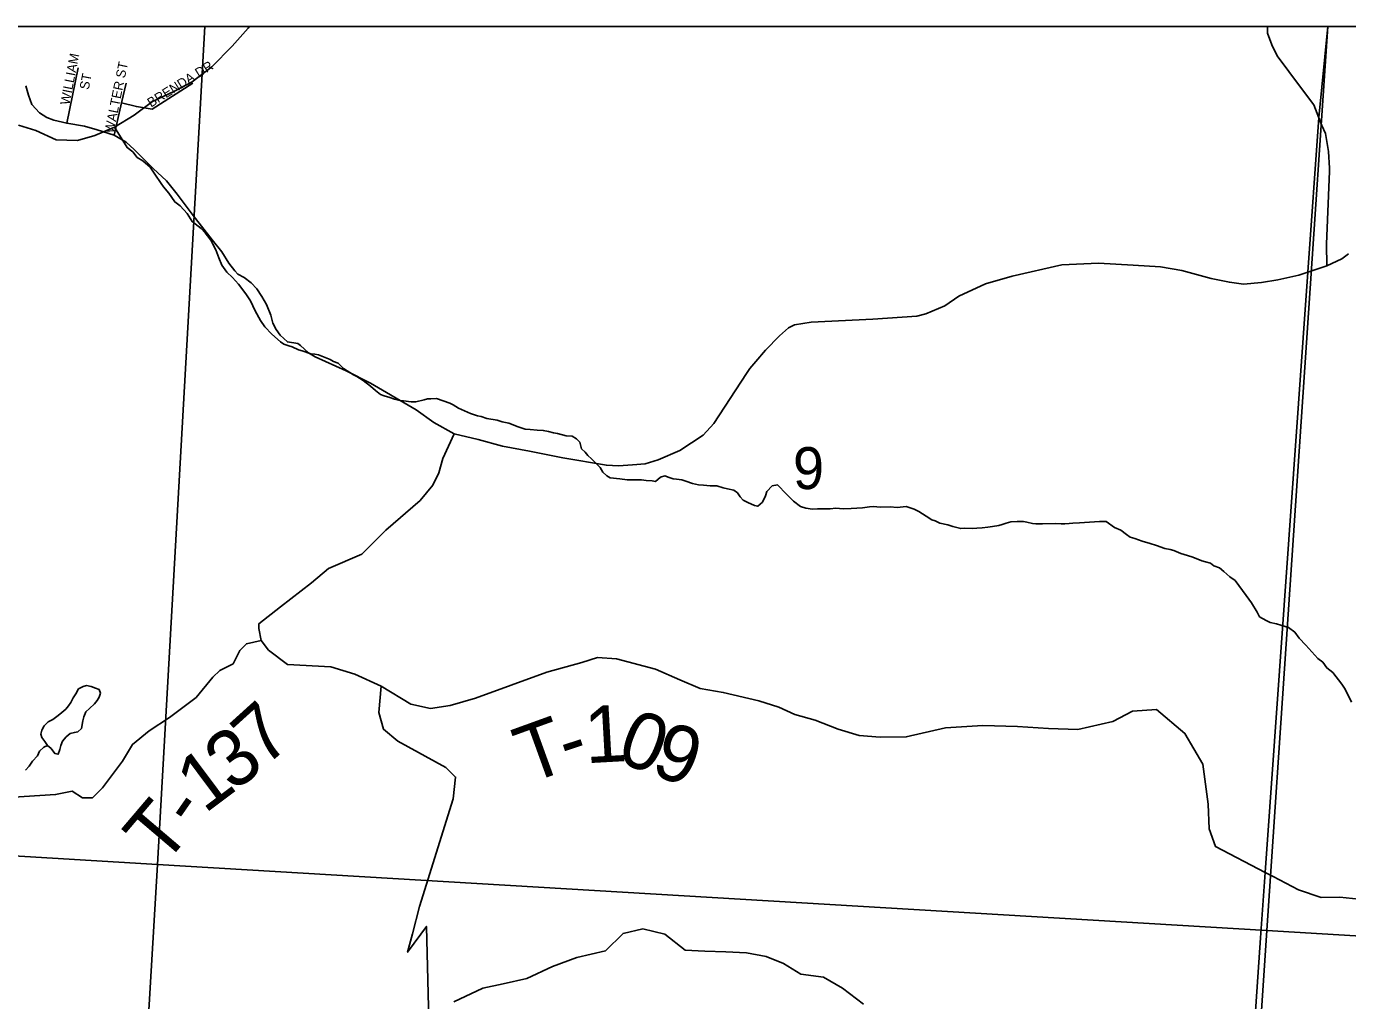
# Model space of a CAD drawing. Extents: x 1949938.81 to 1949945.61, y 152207.65 to 152214.09.
# Drawn here: x 1949941.382 to 1949942.704, y 152213.113 to 152214.087 of the extents above; entities that cross this region are included whole.
import ezdxf

# ---------------------------------------------------------------- set-up
doc = ezdxf.new("R2010")
doc.units = 0
for name, color, linetype in [('GM_X_County', 7, 'Continuous'), ('GM_X_County_Road', 7, 'Continuous'), ('GM_X_Minor_River', 7, 'Continuous'), ('GM_X_Section', 7, 'Continuous'), ('GM_X_Section_Text', 7, 'Continuous'), ('GM_X_State_Route', 7, 'Continuous'), ('GM_X_Township', 7, 'Continuous'), ('GM_X_Township_Road', 7, 'Continuous'), ('GM_X_Township_Road_Text', 7, 'Continuous'), ('GM_X_Township_ROW', 7, 'Continuous'), ('GM_X_Township_Subdivision', 7, 'Continuous'), ('GM_X_Township_Subdivision_Text', 7, 'Continuous')]:
    doc.layers.add(name, color=color, linetype=linetype)

msp = doc.modelspace()

# ---------------------------------------------------------------- linework, layer by layer
at = {"layer": 'GM_X_County'}
msp.add_lwpolyline([(1949945.6069, 152208.8266), (1949945.6069, 152214.0874), (1949938.8069, 152214.0874), (1949938.8069, 152213.1813)], dxfattribs=at)
at = {"layer": 'GM_X_County_Road'}
for points in [[(1949941.7645, 152213.1629), (1949941.7635, 152213.1615), (1949941.7683, 152213.1799), (1949941.7755, 152213.2071), (1949941.8091, 152213.315), (1949941.8115, 152213.3366), (1949941.8019, 152213.3462), (1949941.7539, 152213.3726), (1949941.7395, 152213.3845), (1949941.7347, 152213.4013), (1949941.7371, 152213.4277), (1949941.7107, 152213.4397), (1949941.6867, 152213.4469), (1949941.6435, 152213.4493), (1949941.6244, 152213.4637), (1949941.6172, 152213.4732), (1949941.6148, 152213.4852), (1949941.6148, 152213.49), (1949941.6363, 152213.5068), (1949941.6675, 152213.5308), (1949941.6843, 152213.5452), (1949941.7179, 152213.5596), (1949941.7419, 152213.5836), (1949941.7762, 152213.6134), (1949941.7888, 152213.6286), (1949941.7949, 152213.6409), (1949941.7989, 152213.6553), (1949941.8103, 152213.6801)], [(1949941.7851, 152213.08), (1949941.7823, 152213.1873), (1949941.7645, 152213.1629)]]:
    msp.add_lwpolyline(points, dxfattribs=at)
at = {"layer": 'GM_X_Minor_River'}
for points in [[(1949941.3743, 152213.9886), (1949941.3917, 152213.9832), (1949941.4121, 152213.974), (1949941.4333, 152213.9732), (1949941.4508, 152213.9784), (1949941.4705, 152213.9867), (1949941.4902, 152213.9988), (1949941.5085, 152214.0124), (1949941.5297, 152214.0222), (1949941.5479, 152214.032), (1949941.5677, 152214.0471), (1949941.5882, 152214.0675), (1949941.6042, 152214.0857), (1949941.6053, 152214.0874)], [(1949941.4705, 152213.9867), (1949941.483, 152213.9663), (1949941.4886, 152213.962), (1949941.4931, 152213.9562), (1949941.4987, 152213.9531), (1949941.5062, 152213.9465), (1949941.5106, 152213.9396), (1949941.5169, 152213.9304), (1949941.5195, 152213.9269), (1949941.5247, 152213.9208), (1949941.5306, 152213.9119), (1949941.5362, 152213.908), (1949941.5429, 152213.9003), (1949941.548, 152213.8923), (1949941.557, 152213.8853), (1949941.5611, 152213.881), (1949941.5666, 152213.8737), (1949941.5688, 152213.8695), (1949941.5718, 152213.8638), (1949941.5747, 152213.8561), (1949941.5779, 152213.8485), (1949941.5827, 152213.8416), (1949941.5883, 152213.8362), (1949941.5943, 152213.8296), (1949941.6017, 152213.82), (1949941.6065, 152213.8131), (1949941.6112, 152213.8031), (1949941.6164, 152213.7932), (1949941.6208, 152213.787), (1949941.6279, 152213.7797), (1949941.6364, 152213.7719), (1949941.6398, 152213.7696), (1949941.6447, 152213.768), (1949941.6481, 152213.7668), (1949941.6545, 152213.764), (1949941.6582, 152213.7628), (1949941.6669, 152213.76), (1949941.6707, 152213.7596), (1949941.6745, 152213.7588), (1949941.6793, 152213.7568), (1949941.6861, 152213.7544), (1949941.6895, 152213.7524), (1949941.694, 152213.7505), (1949941.6996, 152213.7454), (1949941.7093, 152213.7388), (1949941.7127, 152213.7372), (1949941.7191, 152213.7333), (1949941.7266, 152213.7275), (1949941.7314, 152213.7233), (1949941.7363, 152213.7194), (1949941.74, 152213.7178), (1949941.7457, 152213.7162), (1949941.7506, 152213.7146), (1949941.7559, 152213.7134), (1949941.7593, 152213.7129), (1949941.7672, 152213.712), (1949941.7717, 152213.712), (1949941.7801, 152213.7141), (1949941.7835, 152213.7148), (1949941.7869, 152213.7151), (1949941.7923, 152213.7154), (1949941.8058, 152213.7106), (1949941.8092, 152213.7091), (1949941.8144, 152213.7056), (1949941.8204, 152213.7028), (1949941.8265, 152213.7004), (1949941.8336, 152213.698), (1949941.837, 152213.6972), (1949941.8427, 152213.6952), (1949941.8532, 152213.6935), (1949941.8581, 152213.6919), (1949941.8649, 152213.6907), (1949941.8743, 152213.6871), (1949941.8811, 152213.6847), (1949941.886, 152213.6842), (1949941.8932, 152213.6837), (1949941.8993, 152213.6833), (1949941.9045, 152213.6824), (1949941.9094, 152213.6808), (1949941.9136, 152213.6804), (1949941.9223, 152213.6779), (1949941.9283, 152213.6775), (1949941.9324, 152213.6751), (1949941.9358, 152213.6716), (1949941.9376, 152213.6651), (1949941.9413, 152213.6617), (1949941.9439, 152213.6582), (1949941.9476, 152213.6551), (1949941.9562, 152213.6462), (1949941.9588, 152213.6416), (1949941.9629, 152213.6378), (1949941.9662, 152213.6358), (1949941.9757, 152213.6349), (1949941.9832, 152213.634), (1949941.9976, 152213.6338), (1949942.0022, 152213.6333), (1949942.0082, 152213.6328), (1949942.0116, 152213.6324), (1949942.0166, 152213.6365)], [(1949942.0166, 152213.6365), (1949942.0208, 152213.6379), (1949942.0253, 152213.6363), (1949942.0291, 152213.6351), (1949942.0325, 152213.6347), (1949942.0378, 152213.6339), (1949942.0419, 152213.6327), (1949942.0487, 152213.6303), (1949942.0544, 152213.629), (1949942.0597, 152213.6286), (1949942.0661, 152213.6281), (1949942.0729, 152213.628), (1949942.0793, 152213.626), (1949942.0835, 152213.6251), (1949942.0899, 152213.6235), (1949942.0936, 152213.6208), (1949942.0962, 152213.6169), (1949942.0992, 152213.6135), (1949942.104, 152213.6111), (1949942.1104, 152213.6084), (1949942.1138, 152213.6075), (1949942.1184, 152213.6116), (1949942.1216, 152213.618), (1949942.1228, 152213.6222), (1949942.1282, 152213.6278), (1949942.1335, 152213.6289), (1949942.1425, 152213.6196), (1949942.1495, 152213.6126), (1949942.1566, 152213.6072), (1949942.1619, 152213.6056), (1949942.1687, 152213.6047), (1949942.1736, 152213.605), (1949942.1861, 152213.6048), (1949942.1918, 152213.6055), (1949942.1994, 152213.605), (1949942.2073, 152213.6052), (1949942.2187, 152213.6058), (1949942.2256, 152213.6068), (1949942.2294, 152213.6071), (1949942.2365, 152213.6066), (1949942.2464, 152213.6068), (1949942.2532, 152213.6064), (1949942.2623, 152213.6073), (1949942.2702, 152213.6046), (1949942.2751, 152213.6022), (1949942.2822, 152213.5975), (1949942.2878, 152213.594), (1949942.2912, 152213.5928), (1949942.2961, 152213.5905), (1949942.304, 152213.5888), (1949942.3089, 152213.5872), (1949942.3168, 152213.5852), (1949942.3203, 152213.5855), (1949942.3286, 152213.5854), (1949942.3328, 152213.5857), (1949942.3384, 152213.5859), (1949942.3438, 152213.5866), (1949942.3487, 152213.5873), (1949942.3548, 152213.5883), (1949942.3582, 152213.5894), (1949942.3624, 152213.5905), (1949942.367, 152213.5919), (1949942.3734, 152213.5922), (1949942.3795, 152213.5921), (1949942.3829, 152213.5917), (1949942.3885, 152213.5904), (1949942.3919, 152213.59), (1949942.3987, 152213.5899), (1949942.4116, 152213.5904), (1949942.4173, 152213.5899), (1949942.4211, 152213.5899), (1949942.4253, 152213.5902), (1949942.4291, 152213.5905), (1949942.4355, 152213.5908), (1949942.4457, 152213.5917), (1949942.4556, 152213.5923), (1949942.4624, 152213.5922), (1949942.4706, 152213.5864), (1949942.477, 152213.5836), (1949942.4826, 152213.5794), (1949942.4864, 152213.5766), (1949942.4909, 152213.5754), (1949942.4984, 152213.5726), (1949942.5063, 152213.5702), (1949942.5127, 152213.5682), (1949942.521, 152213.5654), (1949942.5263, 152213.5642), (1949942.5301, 152213.5634), (1949942.5369, 152213.5602), (1949942.5436, 152213.5582), (1949942.5489, 152213.5566), (1949942.5579, 152213.553), (1949942.5617, 152213.5518), (1949942.5666, 152213.5506), (1949942.57, 152213.5479), (1949942.5756, 152213.5459), (1949942.5801, 152213.5424), (1949942.5861, 152213.537), (1949942.5913, 152213.5331), (1949942.5987, 152213.5231), (1949942.6024, 152213.5181)], [(1949942.6024, 152213.5181), (1949942.6076, 152213.5108), (1949942.6135, 152213.5016), (1949942.6157, 152213.497), (1949942.6224, 152213.4931), (1949942.6265, 152213.4911), (1949942.6326, 152213.4899), (1949942.6371, 152213.4887), (1949942.6446, 152213.4863), (1949942.651, 152213.4816), (1949942.6554, 152213.4755), (1949942.6621, 152213.4685), (1949942.674, 152213.4554), (1949942.6792, 152213.4515), (1949942.6829, 152213.4458), (1949942.6889, 152213.4411), (1949942.6982, 152213.4296), (1949942.7015, 152213.4246), (1949942.7077, 152213.4115)], [(1949941.3812, 152213.3437), (1949941.385, 152213.3475), (1949941.3885, 152213.3527), (1949941.3935, 152213.358), (1949941.3955, 152213.3625), (1949941.3997, 152213.3666), (1949941.4032, 152213.3684), (1949941.4006, 152213.3723), (1949941.3976, 152213.3761), (1949941.3966, 152213.3795), (1949941.3978, 152213.3837), (1949941.4001, 152213.3878), (1949941.404, 152213.392), (1949941.4086, 152213.3941), (1949941.4139, 152213.3982), (1949941.4178, 152213.4012), (1949941.4216, 152213.4046), (1949941.4243, 152213.4079), (1949941.4267, 152213.4113), (1949941.429, 152213.4158), (1949941.4317, 152213.42), (1949941.4345, 152213.4249), (1949941.4391, 152213.4274)], [(1949941.4391, 152213.4274), (1949941.4425, 152213.4281), (1949941.447, 152213.4273), (1949941.4515, 152213.4257), (1949941.4549, 152213.4241), (1949941.4564, 152213.4207), (1949941.4552, 152213.4165), (1949941.4532, 152213.4131), (1949941.4505, 152213.4098), (1949941.4455, 152213.4053), (1949941.4417, 152213.4019), (1949941.4397, 152213.397), (1949941.4388, 152213.3929), (1949941.4372, 152213.3853), (1949941.4337, 152213.382), (1949941.4303, 152213.3813), (1949941.4261, 152213.3802), (1949941.4219, 152213.3768), (1949941.4184, 152213.3727), (1949941.4168, 152213.3682), (1949941.4156, 152213.3644), (1949941.414, 152213.3595), (1949941.4106, 152213.3603), (1949941.4069, 152213.3653), (1949941.4032, 152213.3684)], [(1949941.8099, 152213.1118), (1949941.8388, 152213.1254), (1949941.8592, 152213.1299), (1949941.8827, 152213.1351), (1949941.9085, 152213.1472), (1949941.9328, 152213.1562), (1949941.9616, 152213.1629), (1949941.9791, 152213.1803), (1949941.9988, 152213.1848), (1949942.0208, 152213.1794), (1949942.0411, 152213.1634), (1949942.0608, 152213.1626), (1949942.082, 152213.1618), (1949942.1025, 152213.1609), (1949942.1222, 152213.1571), (1949942.1395, 152213.1502), (1949942.1569, 152213.1395), (1949942.1796, 152213.1364), (1949942.1985, 152213.1257), (1949942.2197, 152213.1097)]]:
    msp.add_lwpolyline(points, dxfattribs=at)
at = {"layer": 'GM_X_Section'}
for p, q in [((1949941.5608, 152214.0874), (1949940.4809, 152214.0874)), ((1949942.6841, 152214.0874), (1949941.5608, 152214.0874)), ((1949943.7893, 152214.0874), (1949942.6841, 152214.0874))]:
    msp.add_line(p, q, dxfattribs=at)
for points in [[(1949940.4809, 152214.0874), (1949940.4294, 152213.3146), (1949941.5133, 152213.2491), (1949941.5608, 152214.0874)], [(1949941.5608, 152214.0874), (1949941.5133, 152213.2491), (1949942.623, 152213.1832), (1949942.6841, 152214.0874)], [(1949942.6841, 152214.0874), (1949942.623, 152213.1832), (1949943.7308, 152213.1166), (1949943.7893, 152214.0874)]]:
    msp.add_lwpolyline(points, dxfattribs=at)
for points in [[(1949941.5133, 152213.2491), (1949941.4524, 152212.2232), (1949940.3609, 152212.2864), (1949940.4294, 152213.3146)], [(1949942.623, 152213.1832), (1949942.5545, 152212.1539), (1949941.4524, 152212.2232), (1949941.5133, 152213.2491)], [(1949943.7308, 152213.1166), (1949943.6665, 152212.0918), (1949942.5545, 152212.1539), (1949942.623, 152213.1832)]]:
    msp.add_lwpolyline(points, close=True, dxfattribs=at)
at = {"layer": 'GM_X_State_Route'}
for points in [[(1949941.3818, 152214.028), (1949941.3843, 152214.0185), (1949941.3878, 152214.0094), (1949941.3953, 152214.0009), (1949941.4026, 152213.9963), (1949941.4097, 152213.9938), (1949941.4226, 152213.9905), (1949941.4402, 152213.9876), (1949941.4531, 152213.984), (1949941.4699, 152213.9788), (1949941.4819, 152213.9715), (1949941.49, 152213.9644), (1949941.509, 152213.9454), (1949941.5224, 152213.933), (1949941.5332, 152213.9195), (1949941.549, 152213.8983), (1949941.5682, 152213.874), (1949941.5776, 152213.862), (1949941.5846, 152213.8505), (1949941.5906, 152213.8429), (1949941.5939, 152213.8395), (1949941.6002, 152213.8364), (1949941.607, 152213.8311), (1949941.6129, 152213.8251), (1949941.6179, 152213.8174), (1949941.6225, 152213.8093), (1949941.6269, 152213.7986), (1949941.6286, 152213.7906), (1949941.632, 152213.7844), (1949941.6362, 152213.7786), (1949941.6434, 152213.7719), (1949941.6536, 152213.7702), (1949941.6565, 152213.7683), (1949941.6644, 152213.7608), (1949941.671, 152213.7571), (1949941.7021, 152213.7429), (1949941.7266, 152213.7305), (1949941.7722, 152213.7041), (1949941.7899, 152213.6913), (1949941.8103, 152213.6801), (1949941.834, 152213.6743), (1949941.8585, 152213.6675), (1949941.8854, 152213.6625), (1949941.9188, 152213.6561), (1949941.9625, 152213.6486), (1949941.9746, 152213.6481), (1949941.9885, 152213.6488), (1949942.0012, 152213.6501), (1949942.0143, 152213.6539), (1949942.0358, 152213.6633), (1949942.0592, 152213.6787), (1949942.0698, 152213.6904), (1949942.1026, 152213.7402), (1949942.1059, 152213.7453), (1949942.112, 152213.7524)], [(1949942.112, 152213.7524), (1949942.1215, 152213.7635), (1949942.1356, 152213.7779), (1949942.1447, 152213.7858), (1949942.1507, 152213.7889), (1949942.1674, 152213.7915), (1949942.2288, 152213.7947), (1949942.2731, 152213.7977), (1949942.2818, 152213.7999), (1949942.3011, 152213.8079), (1949942.3151, 152213.8177), (1949942.3417, 152213.8298), (1949942.3682, 152213.8377), (1949942.4181, 152213.8491), (1949942.4546, 152213.8507), (1949942.4892, 152213.8487), (1949942.5166, 152213.8471), (1949942.5381, 152213.8434), (1949942.5674, 152213.8353), (1949942.5856, 152213.8315), (1949942.5998, 152213.8297), (1949942.6176, 152213.8313), (1949942.6339, 152213.834), (1949942.6552, 152213.8385), (1949942.6641, 152213.8415), (1949942.683, 152213.8479), (1949942.6982, 152213.855), (1949942.7048, 152213.8599)]]:
    msp.add_lwpolyline(points, dxfattribs=at)
at = {"layer": 'GM_X_Township'}
for points in [[(1949942.6839, 152214.0874), (1949938.8069, 152214.0874), (1949938.8069, 152213.1813)], [(1949942.6839, 152214.0874), (1949942.6751, 152213.9962), (1949942.6641, 152213.8415), (1949942.6215, 152213.2412), (1949942.6168, 152213.1758), (1949942.5466, 152212.148), (1949942.0825, 152212.1782), (1949941.5893, 152212.2102), (1949941.4472, 152212.2194), (1949941.3847, 152211.2124)], [(1949941.3847, 152211.2124), (1949941.4472, 152212.2194), (1949941.5893, 152212.2102), (1949942.0825, 152212.1782), (1949942.5466, 152212.148), (1949942.6168, 152213.1758), (1949942.6215, 152213.2412), (1949942.6641, 152213.8415), (1949942.6751, 152213.9962), (1949942.6839, 152214.0874)], [(1949945.6069, 152208.8266), (1949945.6069, 152214.0874), (1949942.6839, 152214.0874)]]:
    msp.add_lwpolyline(points, dxfattribs=at)
at = {"layer": 'GM_X_Township_Road'}
for points in [[(1949942.6856, 152213.9425), (1949942.6857, 152213.9455), (1949942.6847, 152213.9624), (1949942.6816, 152213.9802), (1949942.6782, 152213.9882), (1949942.6751, 152213.9961), (1949942.6701, 152214.0089), (1949942.6567, 152214.0266), (1949942.6335, 152214.058), (1949942.6282, 152214.069), (1949942.6237, 152214.0808), (1949942.6236, 152214.0874)], [(1949942.683, 152213.8479), (1949942.6826, 152213.8695), (1949942.6856, 152213.9425)], [(1949941.4414, 152213.3158), (1949941.4483, 152213.3158), (1949941.4583, 152213.3259), (1949941.4784, 152213.3527), (1949941.4885, 152213.3694), (1949941.5052, 152213.3828), (1949941.5253, 152213.3962), (1949941.5522, 152213.4163), (1949941.5689, 152213.4365), (1949941.5756, 152213.4432), (1949941.589, 152213.4499), (1949941.5957, 152213.4633), (1949941.6024, 152213.47), (1949941.6172, 152213.4732)], [(1949941.7371, 152213.4277), (1949941.7668, 152213.4096), (1949941.7865, 152213.4051), (1949941.8062, 152213.4081), (1949941.8316, 152213.4157), (1949941.9028, 152213.4415), (1949941.9377, 152213.4514), (1949941.9536, 152213.4563), (1949941.9725, 152213.4548), (1949942.0115, 152213.4445), (1949942.0358, 152213.4339), (1949942.0562, 152213.4252), (1949942.0793, 152213.4214), (1949942.1149, 152213.413), (1949942.135, 152213.4065), (1949942.1509, 152213.3993), (1949942.1714, 152213.3936), (1949942.1941, 152213.3845), (1949942.2153, 152213.3781), (1949942.2361, 152213.3766), (1949942.2623, 152213.3769), (1949942.3017, 152213.386), (1949942.3388, 152213.3883), (1949942.3737, 152213.3872), (1949942.4047, 152213.3853), (1949942.4339, 152213.3841), (1949942.4691, 152213.3921), (1949942.4888, 152213.4027), (1949942.5127, 152213.4042), (1949942.5411, 152213.3803), (1949942.5589, 152213.3495), (1949942.5645, 152213.3097), (1949942.5653, 152213.285), (1949942.5717, 152213.2672), (1949942.6215, 152213.2412), (1949942.6293, 152213.2371)], [(1949942.6293, 152213.2371), (1949942.6294, 152213.2371), (1949942.6547, 152213.2239), (1949942.6774, 152213.2163), (1949942.696, 152213.2167), (1949942.7149, 152213.2144), (1949942.7331, 152213.203), (1949942.7585, 152213.1753), (1949942.7895, 152213.1544), (1949942.7971, 152213.1457), (1949942.8096, 152213.1385), (1949942.8221, 152213.135), (1949942.8346, 152213.1335), (1949942.8594, 152213.1251)]]:
    msp.add_lwpolyline(points, dxfattribs=at)
at = {"layer": 'GM_X_Township_ROW'}
msp.add_lwpolyline([(1949941.0358, 152213.2834), (1949941.0423, 152213.283), (1949941.0489, 152213.2842), (1949941.0554, 152213.2876), (1949941.062, 152213.2912), (1949941.0675, 152213.2955), (1949941.074, 152213.2982), (1949941.0777, 152213.2994), (1949941.0818, 152213.3006), (1949941.0861, 152213.3009), (1949941.0932, 152213.3009), (1949941.1022, 152213.2997), (1949941.1138, 152213.3001), (1949941.4114, 152213.3192), (1949941.4281, 152213.3225), (1949941.4382, 152213.3158), (1949941.4414, 152213.3158)], dxfattribs=at)
at = {"layer": 'GM_X_Township_Subdivision'}
for points in [[(1949941.4226, 152213.9905), (1949941.4341, 152214.0459)], [(1949941.4699, 152213.9788), (1949941.4775, 152214.0109), (1949941.482, 152214.0305)], [(1949941.4775, 152214.0109), (1949941.4923, 152214.0072), (1949941.5082, 152214.0048), (1949941.5486, 152214.0307)]]:
    msp.add_lwpolyline(points, dxfattribs=at)

# ---------------------------------------------------------------- texts
at = {"layer": 'GM_X_Section_Text'}
msp.add_text('9', height=0.0419, rotation=0, dxfattribs=at).set_placement((1949942.149, 152213.6247))
at = {"layer": 'GM_X_Township_Road_Text'}
for s, rotation, p in [('7', 42.1376, (1949941.6205, 152213.3455)), ('T', 19.8984, (1949941.8841, 152213.3295)), ('1', 3.2092, (1949941.9419, 152213.3504)), ('0', 338.9561, (1949941.9706, 152213.3534)), ('3', 37.7367, (1949941.5892, 152213.321)), ('9', 340.7228, (1949942.0051, 152213.3401)), ('-', 18.3664, (1949941.9237, 152213.3438)), ('1', 36.7731, (1949941.5604, 152213.2994)), ('T', 49.6158, (1949941.5192, 152213.2466)), ('-', 55.1548, (1949941.5504, 152213.2837))]:
    msp.add_text(s, height=0.0568, rotation=rotation, dxfattribs=at).set_placement(p)
at = {"layer": 'GM_X_Township_Subdivision_Text'}
for s, rotation, p in [('WILLIAM', 78.8733, (1949941.4252, 152214.0083)), ('WALTER ST', 78.4066, (1949941.4694, 152213.98)), ('BRENDA DR', 31.9307, (1949941.5069, 152214.0061)), ('ST', 79.3727, (1949941.4446, 152214.0236))]:
    msp.add_text(s, height=0.00947, rotation=rotation, dxfattribs=at).set_placement(p)

doc.saveas('drawing.dxf')
